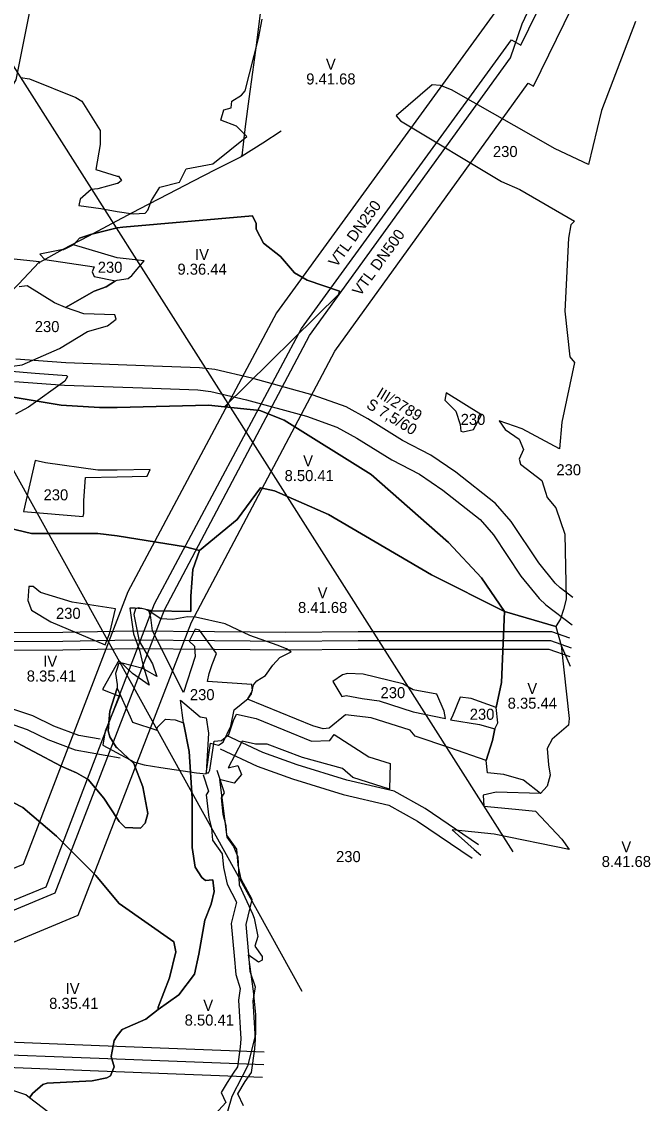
# Model space of a CAD drawing. Extents: x -694504 to -690518, y -983661 to -978958.
# Drawn here: x -691377 to -690523, y -982051 to -980583 of the extents above; entities that cross this region are included whole.
import ezdxf

# ---------------------------------------------------------------- set-up
doc = ezdxf.new("R2010")
doc.units = 0
for name, color, linetype in [('bezpečnostní pásmo', 7, 'Continuous'), ('BPEJ', 7, 'Continuous'), ('kabelové a venkovní rozvody telefonu', 7, 'Continuous'), ('lokální biocentra', 7, 'Continuous'), ('lokální biokoridory', 7, 'Continuous'), ('ochranné pásmo radioreleové trasy', 7, 'Continuous'), ('ochranné pásmo silnic', 7, 'Continuous'), ('ochranné pásmo vedení', 7, 'Continuous'), ('OP vodního zdroje 2 stupně', 7, 'Continuous'), ('třídy přednosti v ochraně ZP', 7, 'Continuous'), ('vedení NN', 7, 'Continuous'), ('vedení VN 35kV', 7, 'Continuous'), ('vedení VVN 110kV', 7, 'Continuous'), ('VTL plynovod', 7, 'Continuous')]:
    doc.layers.add(name, color=color, linetype=linetype)

msp = doc.modelspace()

# ---------------------------------------------------------------- linework, layer by layer
at = {"layer": 'bezpečnostní pásmo'}
for points in [[(-690673.7, -980441.7), (-690734.3, -980570.8), (-690734.4, -980570.8), (-691030.9, -980978.4), (-691232.9, -981356.8), (-691374.8, -981727), (-691755.3, -981882.6), (-691867.9, -982087.1), (-691866.5, -982152.1)], [(-691698.8, -981974.2), (-691698.8, -981974.2), (-691689.8, -981958.1), (-691300.2, -981796), (-691146.3, -981397.9), (-690951.9, -981030.3), (-690689.1, -980666.7), (-690682.1, -980670.7), (-690598.6, -980500.1)]]:
    msp.add_lwpolyline(points, dxfattribs=at)
at = {"layer": 'BPEJ'}
for p, q in [((-690644.4, -981429.8), (-690632.1, -981457.7)), ((-690762.4, -981706.8), (-690753.6, -981714.2))]:
    msp.add_line(p, q, dxfattribs=at)
for points in [[(-691378.4, -980658.8), (-691366.4, -980660.8), (-691303.4, -980685.8), (-691295.4, -980690.8), (-691270.4, -980730.8), (-691270.4, -980749.8), (-691276.4, -980783.8), (-691247.4, -980792.8), (-691245.4, -980792.8), (-691241.4, -980798.8), (-691246.4, -980802.8), (-691247.4, -980802.8), (-691273.4, -980809.8), (-691282.4, -980810.8), (-691297.4, -980823.8), (-691299.4, -980832.8), (-691269.4, -980836.8), (-691247.4, -980840.8), (-691225.4, -980843.8), (-691209.4, -980842.8), (-691205.4, -980838.8), (-691200.4, -980825.8), (-691189.4, -980807.8), (-691162.4, -980800.8), (-691153.4, -980782.8), (-691117.4, -980775.8), (-691071.4, -980738.8), (-691085.4, -980724.8), (-691106.4, -980716.8), (-691102.4, -980702.8), (-691092.4, -980699.8), (-691091.4, -980690.8), (-691078.4, -980682.8), (-691073.4, -980676.8), (-691055.4, -980605.8), (-691050.4, -980579.8)], [(-690543.4, -980582.8), (-690589.4, -980703.8), (-690607.4, -980776.8), (-690652.4, -980755.8), (-690793.4, -980675.8), (-690808.4, -980669.8), (-690819.4, -980668.8), (-690868.4, -980710.8), (-690862.4, -980717.8), (-690725.4, -980799.8), (-690700.4, -980810.8), (-690626.4, -980853.8), (-690626.4, -980853.8)], [(-691389.4, -981050.8), (-691376.4, -981048.8), (-691325.4, -981026.8), (-691287.4, -981003.8), (-691260.4, -980995.8), (-691248.4, -980986.8), (-691250.4, -980980.8), (-691292.4, -980979.8), (-691317.4, -980970.8), (-691278.4, -980948.8), (-691262.4, -980942.8), (-691249.4, -980934.8), (-691247.4, -980933.8), (-691232.4, -980931.8), (-691227.4, -980927.8), (-691210.4, -980907.8), (-691247.4, -980903.8), (-691306.4, -980885.8), (-691298.4, -980876.8), (-691283.4, -980871.8), (-691247.4, -980862.8), (-691239.4, -980861.8), (-691063.4, -980846.8), (-691058.4, -980856.8), (-691058.4, -980864.8), (-691048.4, -980883.8), (-691025.4, -980901.8), (-691006.4, -980923.8), (-690989.4, -980933.8), (-690945.4, -980948.8), (-690946.4, -980952.8), (-691101.4, -981105.8), (-691101.4, -981105.8), (-691123.4, -981103.8), (-691247.4, -981106.8), (-691271.4, -981106.8), (-691323.4, -981103.8), (-691388.4, -981092.8)], [(-690626.4, -980853.8), (-690631.4, -980858.8), (-690634.4, -980876.8), (-690639.4, -980975.8), (-690632.4, -981037.8), (-690626.4, -981045.8), (-690643.4, -981126.8), (-690646.4, -981162.8), (-690697.4, -981135.8), (-690728.4, -981124.8), (-690720.4, -981136.8), (-690701.4, -981149.8), (-690695.4, -981163.8), (-690701.4, -981176.8), (-690699.4, -981183.8), (-690670.4, -981205.8), (-690665.4, -981221.8), (-690663.4, -981228.8), (-690651.4, -981242.8), (-690639.4, -981278.8), (-690637.4, -981366.8), (-690641.4, -981380.8), (-690645.4, -981393.8), (-690651.4, -981403.8), (-690721.4, -981383.8), (-690752.4, -981337.8), (-690797.4, -981289.8), (-690902.4, -981197.8), (-691020.4, -981123.8), (-691053.4, -981110.8), (-691101.4, -981105.8), (-690946.4, -980952.8), (-690945.4, -980948.8), (-690989.4, -980933.8), (-691006.4, -980923.8), (-691025.4, -980901.8), (-691048.4, -980883.8), (-691058.4, -980864.8), (-691058.4, -980856.8), (-691063.4, -980846.8), (-691239.4, -980861.8), (-691247.4, -980862.8), (-691283.4, -980871.8), (-691298.4, -980876.8), (-691306.4, -980885.8), (-691318.4, -980891.8), (-691352.4, -980898.8), (-691345.4, -980905.8), (-691278.4, -980915.8), (-691281.4, -980922.8), (-691278.4, -980928.8), (-691249.4, -980934.8), (-691262.4, -980942.8), (-691278.4, -980948.8), (-691317.4, -980970.8), (-691332.4, -980964.8), (-691369.4, -980941.8), (-691380.4, -980942.8)], [(-691388.4, -981092.8), (-691323.4, -981103.8), (-691271.4, -981106.8), (-691247.4, -981106.8), (-691123.4, -981103.8), (-691101.4, -981105.8), (-691101.4, -981105.8), (-691053.4, -981110.8), (-691020.4, -981123.8), (-690902.4, -981197.8), (-690797.4, -981289.8), (-690752.4, -981337.8), (-690721.4, -981383.8), (-690820.4, -981333.8), (-690960.4, -981251.8), (-691033.4, -981219.8), (-691052.4, -981215.8), (-691084.4, -981258.8), (-691135.4, -981300.8), (-691154.4, -981295.8), (-691247.4, -981280.8), (-691273.4, -981277.8), (-691363.4, -981277.8), (-691447.4, -981257.8)], [(-691447.4, -981257.8), (-691363.4, -981277.8), (-691273.4, -981277.8), (-691247.4, -981280.8), (-691154.4, -981295.8), (-691135.4, -981300.8), (-691144.4, -981326.8), (-691147.4, -981362.8), (-691147.4, -981383.8), (-691199.4, -981382.8), (-691204.4, -981381.8), (-691218.4, -981378.8), (-691222.4, -981379.8), (-691224.4, -981387.8), (-691217.4, -981423.8), (-691199.4, -981454.8), (-691193.4, -981471.8), (-691212.4, -981460.8), (-691240.4, -981453.8), (-691245.4, -981454.8), (-691247.4, -981460.8), (-691249.4, -981467.8), (-691247.4, -981482.8), (-691247.4, -981487.8), (-691257.4, -981518.8), (-691259.4, -981545.8), (-691257.4, -981553.8), (-691248.4, -981567.8), (-691247.4, -981568.8), (-691224.4, -981589.8), (-691212.4, -981621.8), (-691205.4, -981657.8), (-691209.4, -981670.8), (-691215.4, -981677.8), (-691236.4, -981676.8), (-691244.4, -981668.8), (-691247.4, -981664.8), (-691265.4, -981636.8), (-691286.4, -981611.8), (-691302.4, -981602.8), (-691323.4, -981593.8), (-691398.4, -981553.8)], [(-691247.4, -981487.8), (-691229.4, -981526.8), (-691226.4, -981533.8), (-691193.4, -981544.8), (-691192.4, -981540.8), (-691181.4, -981529.8), (-691168.4, -981530.8), (-691157.4, -981534.8), (-691149.4, -981573.8), (-691145.4, -981636.8), (-691145.4, -981703.8), (-691141.4, -981730.8), (-691132.4, -981744.8), (-691127.4, -981748.8), (-691117.4, -981747.8), (-691115.4, -981763.8), (-691119.4, -981780.8), (-691128.4, -981802.8), (-691136.4, -981848.8), (-691142.4, -981875.8), (-691163.4, -981903.8), (-691191.4, -981923.8), (-691191.4, -981920.8), (-691176.4, -981880.8), (-691167.4, -981845.8), (-691170.4, -981831.8), (-691244.4, -981779.8), (-691247.4, -981776.8), (-691276.4, -981741.8), (-691329.4, -981688.8), (-691375.4, -981649.8), (-691388.4, -981642.8)], [(-691247.4, -981568.8), (-691248.4, -981567.8), (-691257.4, -981553.8), (-691259.4, -981545.8), (-691257.4, -981518.8), (-691247.4, -981487.8), (-691247.4, -981487.8)], [(-691324.4, -982075.8), (-691366.4, -982043.8), (-691366.4, -982043.8), (-691362.4, -982037.8), (-691348.4, -982025.8), (-691342.4, -982023.8), (-691281.4, -982020.8), (-691261.4, -982016.8), (-691256.4, -982013.8), (-691251.4, -982001.8), (-691255.4, -981987.8), (-691251.4, -981965.8), (-691247.4, -981959.8), (-691240.4, -981950.8), (-691208.4, -981936.8), (-691191.4, -981923.8), (-691163.4, -981903.8), (-691142.4, -981875.8), (-691136.4, -981848.8), (-691128.4, -981802.8), (-691119.4, -981780.8), (-691115.4, -981763.8), (-691117.4, -981747.8), (-691127.4, -981748.8), (-691132.4, -981744.8), (-691141.4, -981730.8), (-691145.4, -981703.8), (-691145.4, -981636.8), (-691149.4, -981573.8), (-691157.4, -981534.8), (-691161.4, -981503.8), (-691134.4, -981526.8), (-691126.4, -981527.8), (-691123.4, -981548.8), (-691126.4, -981602.8), (-691123.4, -981602.8), (-691121.4, -981598.8), (-691115.4, -981559.8), (-691105.4, -981558.8), (-691095.4, -981550.8), (-691089.4, -981531.8), (-691085.4, -981522.8), (-691058.4, -981528.8), (-690983.4, -981559.8), (-690958.4, -981558.8), (-690952.4, -981550.8), (-690905.4, -981580.8), (-690876.4, -981589.8), (-690877.4, -981624.8), (-690927.4, -981608.8), (-690941.4, -981596.8), (-690995.4, -981581.8), (-691043.4, -981563.8), (-691059.4, -981563.8), (-691077.4, -981559.8), (-691096.4, -981595.8), (-691083.4, -981592.8), (-691078.4, -981604.8), (-691088.4, -981616.8), (-691108.4, -981611.8), (-691098.4, -981689.8), (-691089.4, -981702.8), (-691083.4, -981716.8), (-691081.4, -981754.8), (-691063.4, -981793.8), (-691061.4, -981799.8), (-691056.4, -981824.8), (-691060.4, -981837.8), (-691050.4, -981851.8), (-691050.4, -981856.8), (-691055.4, -981859.8), (-691069.4, -981849.8), (-691062.4, -981898.8), (-691059.4, -981930.8), (-691059.4, -981957.8), (-691070.4, -982000.8), (-691077.4, -982014.8), (-691091.4, -982041.8), (-691103.4, -982082.8)], [(-691398.4, -981553.8), (-691323.4, -981593.8), (-691302.4, -981602.8), (-691286.4, -981611.8), (-691265.4, -981636.8), (-691247.4, -981664.8), (-691244.4, -981668.8), (-691236.4, -981676.8), (-691215.4, -981677.8), (-691209.4, -981670.8), (-691205.4, -981657.8), (-691212.4, -981621.8), (-691224.4, -981589.8), (-691247.4, -981568.8)], [(-690672.4, -981630.8), (-690732.4, -981628.8), (-690750.4, -981632.8), (-690749.4, -981647.8), (-690706.4, -981651.8), (-690679.4, -981654.8), (-690643.4, -981692.8), (-690633.4, -981706.8), (-690735.4, -981685.8), (-690792.4, -981679.8), (-690762.4, -981706.8)], [(-691388.4, -981642.8), (-691375.4, -981649.8), (-691329.4, -981688.8), (-691276.4, -981741.8), (-691247.4, -981776.8), (-691244.4, -981779.8), (-691170.4, -981831.8), (-691167.4, -981845.8), (-691176.4, -981880.8), (-691191.4, -981920.8), (-691191.4, -981923.8), (-691191.4, -981923.8), (-691208.4, -981936.8), (-691240.4, -981950.8), (-691247.4, -981959.8), (-691251.4, -981965.8), (-691255.4, -981987.8), (-691251.4, -982001.8), (-691256.4, -982013.8), (-691261.4, -982016.8), (-691281.4, -982020.8), (-691342.4, -982023.8), (-691348.4, -982025.8), (-691362.4, -982037.8), (-691366.4, -982043.8), (-691371.4, -982039.8), (-691445.4, -982014.8)]]:
    msp.add_lwpolyline(points, dxfattribs=at)
for points in [[(-690763.4, -981136.8), (-690752.4, -981116.8), (-690800.4, -981086.8), (-690802.4, -981096.8), (-690787.4, -981111.8), (-690781.4, -981129.8), (-690780.4, -981138.8), (-690777.4, -981139.8), (-690763.4, -981136.8)], [(-691344.4, -981181.8), (-691358.4, -981178.8), (-691374.4, -981247.8), (-691293.4, -981254.8), (-691292.4, -981250.8), (-691292.4, -981232.8), (-691290.4, -981201.8), (-691247.4, -981200.8), (-691206.4, -981199.8), (-691202.4, -981190.8), (-691247.4, -981191.8), (-691273.4, -981191.8), (-691344.4, -981181.8)], [(-690721.4, -981383.8), (-690725.4, -981479.8), (-690732.4, -981513.8), (-690766.4, -981501.8), (-690781.4, -981499.8), (-690792.4, -981526.8), (-690794.4, -981530.8), (-690755.4, -981536.8), (-690734.4, -981542.8), (-690737.4, -981558.8), (-690746.4, -981585.8), (-690795.4, -981568.8), (-690842.4, -981552.8), (-690849.4, -981544.8), (-690902.4, -981527.8), (-690937.4, -981523.8), (-690959.4, -981541.8), (-690967.4, -981542.8), (-690981.4, -981538.8), (-691070.4, -981502.8), (-691063.4, -981490.8), (-691064.4, -981482.8), (-691124.4, -981478.8), (-691122.4, -981467.8), (-691118.4, -981455.8), (-691112.4, -981440.8), (-691135.4, -981408.8), (-691141.4, -981407.8), (-691149.4, -981423.8), (-691142.4, -981430.8), (-691141.4, -981444.8), (-691157.4, -981493.8), (-691199.4, -981409.8), (-691201.4, -981391.8), (-691204.4, -981381.8), (-691199.4, -981382.8), (-691147.4, -981383.8), (-691147.4, -981362.8), (-691144.4, -981326.8), (-691135.4, -981300.8), (-691084.4, -981258.8), (-691052.4, -981215.8), (-691033.4, -981219.8), (-690960.4, -981251.8), (-690820.4, -981333.8), (-690721.4, -981383.8)], [(-691257.4, -981412.8), (-691249.4, -981379.8), (-691308.4, -981370.8), (-691351.4, -981357.8), (-691361.4, -981349.8), (-691367.4, -981349.8), (-691368.4, -981368.8), (-691363.4, -981381.8), (-691337.4, -981397.8), (-691263.4, -981428.8), (-691257.4, -981412.8)], [(-690651.4, -981403.8), (-690644.4, -981429.8), (-690633.4, -981528.8), (-690634.4, -981537.8), (-690656.4, -981556.8), (-690663.4, -981569.8), (-690661.4, -981591.8), (-690659.4, -981605.8), (-690663.4, -981620.8), (-690672.4, -981630.8), (-690695.4, -981612.8), (-690722.4, -981604.8), (-690744.4, -981602.8), (-690746.4, -981585.8), (-690737.4, -981558.8), (-690734.4, -981542.8), (-690730.4, -981534.8), (-690732.4, -981513.8), (-690725.4, -981479.8), (-690721.4, -981383.8), (-690651.4, -981403.8)], [(-690813.4, -981495.8), (-690845.4, -981489.8), (-690859.4, -981481.8), (-690913.4, -981468.8), (-690934.4, -981467.8), (-690941.4, -981469.8), (-690954.4, -981478.8), (-690942.4, -981498.8), (-690936.4, -981497.8), (-690914.4, -981501.8), (-690891.4, -981504.8), (-690845.4, -981519.8), (-690801.4, -981528.8), (-690803.4, -981518.8), (-690813.4, -981495.8)]]:
    msp.add_lwpolyline(points, close=True, dxfattribs=at)
at = {"layer": 'kabelové a venkovní rozvody telefonu'}
msp.add_lwpolyline([(-691396.2, -981057), (-691358.4, -981060), (-691316.1, -981063.2), (-691314.5, -981064.8), (-691318.5, -981071.1), (-691367.8, -981106.5), (-691385.1, -981115.9)], dxfattribs=at)
at = {"layer": 'lokální biocentra'}
msp.add_lwpolyline([(-691266.6, -981564.9), (-691223.9, -981588.2), (-691210.8, -981591.8), (-691187.9, -981595.3), (-691139.6, -981602.4), (-691126.2, -981603.9), (-691120.5, -981562.4), (-691117.1, -981563.1), (-691109.5, -981565.1), (-691103.1, -981561), (-691093.1, -981539.2), (-691088.6, -981517), (-691069.4, -981501.6), (-691065, -981495.2), (-691062.1, -981483.3), (-691057.7, -981477.9), (-691045.8, -981470.7), (-691036, -981456.7), (-691026.3, -981446.3), (-691010.8, -981438.3), (-691017.1, -981434.4), (-691030.1, -981429.5), (-691067.3, -981416.2), (-691100.7, -981400.2), (-691141.1, -981391.2), (-691151.8, -981390.8), (-691171.7, -981394.6), (-691187.8, -981393.5), (-691203.7, -981383.2), (-691208.4, -981381), (-691213.9, -981379.6), (-691218.6, -981379.4), (-691222.9, -981379.3), (-691230.2, -981379), (-691225.1, -981414.1), (-691216.9, -981436.3), (-691212.1, -981457.4), (-691203.7, -981483.5), (-691226.2, -981468), (-691245, -981450), (-691246.4, -981452.5), (-691265, -981485.3), (-691267.3, -981489.3), (-691244, -981498.7), (-691263.4, -981546.2), (-691266.3, -981561.8)], close=True, dxfattribs=at)
at = {"layer": 'lokální biokoridory'}
for points in [[(-691270.2, -981557), (-691299.1, -981551.8), (-691333.3, -981539.2), (-691361.6, -981525.1), (-691402.3, -981511.5)], [(-691407.7, -981530.8), (-691369.3, -981543.7), (-691341.2, -981557.6), (-691304.4, -981571.2), (-691243.1, -981582.1)], [(-690756.5, -981700.2), (-690829.1, -981651.1), (-690870.9, -981627.5), (-690935.3, -981612.8), (-691002.8, -981591.9), (-691049.5, -981574.9), (-691098.9, -981552)], [(-691107.3, -981570.1), (-691057.2, -981593.4), (-691009.2, -981610.8), (-690940.5, -981632.1), (-690878.2, -981646.3), (-690839.6, -981668.1), (-690765.1, -981718.4)], [(-691130.3, -981605.5), (-691123.4, -981627.4), (-691126.2, -981632.5), (-691122.9, -981663.1), (-691119, -981677.9), (-691117.7, -981694.2), (-691104.6, -981712.7), (-691102.9, -981731), (-691098, -981753.7), (-691085.2, -981778.3), (-691092.3, -981807.1), (-691088.4, -981851.1), (-691086.2, -981876.2), (-691080.1, -981895.3), (-691082.5, -981911), (-691079.4, -981963.7), (-691080.2, -981975.1), (-691083.8, -982001.9), (-691089.9, -982010.4), (-691097.7, -982022.8), (-691106.1, -982036.6), (-691099.6, -982050.1), (-691119.2, -982071.3)], [(-691075.7, -982054.5), (-691083.6, -982038.2), (-691073.3, -982021.6), (-691064.7, -982009.5), (-691060.3, -981977.2), (-691059.3, -981963.9), (-691062.4, -981911.9), (-691059.6, -981893.7), (-691066.5, -981872.3), (-691068.4, -981849.4), (-691072.1, -981808.7), (-691064.1, -981774.7), (-691079, -981746.8), (-691083, -981728.1), (-691084.9, -981706.3), (-691098.2, -981687.2), (-691099.2, -981674.5), (-691103.2, -981659.4), (-691105.6, -981636.6), (-691101.7, -981629.6), (-691111.3, -981599.4)]]:
    msp.add_lwpolyline(points, dxfattribs=at)
at = {"layer": 'ochranné pásmo radioreleové trasy'}
for p, q in [((-692444.8, -978981.7), (-690710.2, -981710)), ((-692605.8, -978994.5), (-690996.6, -981898.9))]:
    msp.add_line(p, q, dxfattribs=at)
at = {"layer": 'ochranné pásmo silnic'}
for points in [[(-690628.5, -981364.5), (-690645.8, -981351.4), (-690652.5, -981345.2), (-690674.9, -981317.7), (-690712.4, -981261.7), (-690733.4, -981237.2), (-690787.4, -981194.6), (-690821.5, -981171.6), (-690859.6, -981151.6), (-690906.9, -981122.3), (-690936.5, -981106), (-690981.2, -981089.9), (-691064.3, -981067.1), (-691114.7, -981055.4), (-691135.4, -981052.8), (-691198.5, -981050.6), (-691317, -981046.3), (-691384.7, -981041.3)], [(-691386.6, -981071.3), (-691318.7, -981076.3), (-691199.5, -981080.6), (-691137.9, -981082.7), (-691120, -981085), (-691071.6, -981096.2), (-690990.3, -981118.5), (-690948.9, -981133.4), (-690922, -981148.2), (-690874.5, -981177.7), (-690836.9, -981197.4), (-690805.1, -981218.8), (-690754.3, -981258.9), (-690736.4, -981279.8), (-690699.1, -981335.6), (-690674.4, -981365.9), (-690665.1, -981374.4), (-690629.3, -981401.7)]]:
    msp.add_lwpolyline(points, dxfattribs=at)
at = {"layer": 'ochranné pásmo vedení'}
for points in [[(-692098.8, -981564.6), (-692085.7, -981520.2), (-692075.7, -981482.1), (-692062.7, -981435.2), (-692049.7, -981390.2), (-692040.6, -981358.3), (-691971, -981369.6), (-691893, -981383.6), (-691578.4, -981435.3), (-691506, -981436.1), (-691403.8, -981436.1), (-691320.9, -981435.7), (-691226.9, -981433.8), (-691115.1, -981434.8), (-691018, -981435.8), (-690919.9, -981434.8), (-690865, -981434.8), (-690798, -981434.8), (-690720.4, -981434.8), (-690661, -981434.8), (-690632.7, -981444.7)], [(-690632.8, -981419.7), (-690657, -981411.2), (-690720.4, -981411.3), (-690798, -981411.3), (-690865, -981411.3), (-690920.1, -981411.3), (-691018, -981412.2), (-691114.9, -981411.3), (-691227.1, -981410.2), (-691321.1, -981412.3), (-691403.8, -981412.6), (-691505.9, -981412.6), (-691553.7, -981412.1), (-691541.1, -981395.6)], [(-691047.7, -981981.6), (-691271.2, -981973.1), (-691442.4, -981966.6), (-691696.3, -981955.7), (-691917.9, -981947.7), (-692137.4, -981938.6), (-692397.8, -981927.4), (-692632.6, -981919), (-692886.9, -981909.2), (-693061.3, -981902.2)], [(-693056.9, -981936.4), (-692888.2, -981943.2), (-692633.8, -981953), (-692399.1, -981961.3), (-692138.8, -981972.6), (-691919.2, -981981.6), (-691697.6, -981989.7), (-691443.7, -982000.5), (-691272.5, -982007.1), (-691049.8, -982015.6)]]:
    msp.add_lwpolyline(points, dxfattribs=at)
at = {"layer": 'OP vodního zdroje 2 stupně'}
msp.add_lwpolyline([(-691584.7, -979993.1), (-691645.5, -980041.6), (-691739.8, -980384.6), (-691760.1, -980498.4), (-691750.5, -980690.4), (-691426.7, -980730.4), (-691384.5, -980661.8), (-691268.8, -980085.8), (-691256.8, -980025.6)], close=True, dxfattribs=at)
at = {"layer": 'vedení NN'}
for points in [[(-691078.6, -980765.7), (-691078.7, -980765.5), (-691077.6, -980765), (-691073, -980725.4), (-691067.9, -980687.6), (-691063.1, -980651.5), (-691057.7, -980612), (-691053.1, -980575.1), (-691048.7, -980539.2), (-691044.2, -980503.7)], [(-691077.4, -980765.3), (-691049.4, -980747.6), (-691024.7, -980731.4)], [(-691320.6, -980892), (-691285.8, -980873.7), (-691247.7, -980853.4), (-691216.7, -980837), (-691177.5, -980816.6), (-691143.7, -980798.9), (-691113.7, -980783.7), (-691077.4, -980765.4)], [(-691078.6, -980765.7), (-691078.6, -980765.9), (-691077.4, -980765.4)], [(-691352.9, -980910.4), (-691352.8, -980909.2), (-691391.6, -980904.9), (-691429.8, -980900.8), (-691470.1, -980896.6), (-691509, -980892.2), (-691547.7, -980888.1)], [(-691352.9, -980910.4), (-691352.5, -980910.4), (-691352.4, -980909.3), (-691320.6, -980892)], [(-691319.8, -980893.1), (-691320.6, -980892)], [(-691456.7, -981018.2), (-691433.2, -980993), (-691408.2, -980967), (-691381.4, -980939.4), (-691353.3, -980909.5), (-691353.3, -980910.4), (-691352.9, -980910.4)]]:
    msp.add_lwpolyline(points, dxfattribs=at)
at = {"layer": 'vedení VN 35kV'}
msp.add_lwpolyline([(-692836.2, -981198.9), (-692742.1, -981216.5), (-692657.7, -981232.3), (-692588, -981245), (-692503, -981261), (-692435, -981273), (-692237, -981310), (-692134, -981329), (-692049, -981345), (-691969, -981358), (-691891, -981372), (-691577.3, -981423.6), (-691505.9, -981424.4), (-691403.8, -981424.3), (-691321, -981424), (-691227, -981422), (-691115, -981423), (-691018, -981424), (-690920, -981423), (-690865, -981423), (-690798, -981423), (-690720.4, -981423.1), (-690659, -981423), (-690630.9, -981432.8)], dxfattribs=at)
at = {"layer": 'vedení VVN 110kV'}
msp.add_lwpolyline([(-693059.7, -981919.3), (-692887.5, -981926.2), (-692633.2, -981936), (-692398.5, -981944.3), (-692138.1, -981955.6), (-691918.6, -981964.7), (-691697, -981972.7), (-691443, -981983.5), (-691271.9, -981990.1), (-691048.2, -981998.6)], dxfattribs=at)
at = {"layer": 'VTL plynovod'}
for points in [[(-691827.1, -982121.4), (-691827.6, -982097), (-691727.1, -981914.3), (-691343.6, -981757.4), (-691196.4, -981373.4), (-690997, -980999.7), (-690711.8, -980607.8), (-690699.3, -980614.9), (-690634.5, -980482.5)], [(-691814.1, -982124.6), (-691815.4, -982100.9), (-691717.9, -981926.4), (-691331.3, -981765.6), (-691182.8, -981381.3), (-690986, -981009.1), (-690713.3, -980632), (-690697.3, -980585.9), (-690644.7, -980474.1)]]:
    msp.add_lwpolyline(points, dxfattribs=at)

# ---------------------------------------------------------------- texts
at = {"layer": 'ochranné pásmo silnic'}
for s, p in [('III/2789', (-690896.4, -981091.4)), ('S 7,5/60', (-690910.1, -981106.5))]:
    msp.add_text(s, height=15, rotation=329, dxfattribs=at).set_placement(p)
at = {"layer": 'třídy přednosti v ochraně ZP'}
for s, p in [('V', (-690963.8, -980648.3)), ('9.41.68', (-690990.5, -980668.3)), ('230', (-690737, -980766.8)), ('IV', (-691141.5, -980906.5)), ('230', (-691273.6, -980923.9)), ('9.36.44', (-691165.4, -980926.5)), ('230', (-691359.1, -981004.4)), ('230', (-690780.8, -981130.4)), ('V', (-690994.7, -981186.7)), ('230', (-690650.8, -981198.8)), ('8.50.41', (-691019.9, -981206.7)), ('230', (-691347.2, -981232.8)), ('V', (-690975, -981365.7)), ('230', (-691330.3, -981393.6)), ('8.41.68', (-691001.7, -981385.7)), ('IV', (-691347.6, -981458.7)), ('8.35.41', (-691370, -981478.7)), ('V', (-690690.3, -981495.6)), ('230', (-691148.5, -981504)), ('230', (-690889.6, -981501.3)), ('8.35.44', (-690717, -981515.6)), ('230', (-690768.5, -981530.6)), ('V', (-690562.6, -981710.5)), ('230', (-690950, -981723.8)), ('8.41.68', (-690589.3, -981730.5)), ('IV', (-691317.2, -981903)), ('8.35.41', (-691339.6, -981923)), ('V', (-691130.3, -981925.7)), ('8.50.41', (-691155.6, -981945.7))]:
    msp.add_text(s, height=15, dxfattribs=at).set_placement(p)
at = {"layer": 'VTL plynovod'}
for s, p in [('VTL DN250', (-690949.5, -980917.4)), ('VTL DN500', (-690917.3, -980956.6))]:
    msp.add_text(s, height=15, rotation=54, dxfattribs=at).set_placement(p)

doc.saveas('drawing.dxf')
